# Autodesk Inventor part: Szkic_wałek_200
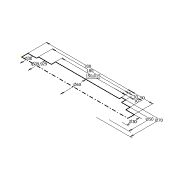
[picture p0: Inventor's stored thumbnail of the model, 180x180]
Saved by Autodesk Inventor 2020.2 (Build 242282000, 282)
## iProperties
Created: 2005-01
Part Number: Szkic_wałek_200
Document SubType Name: Modeling
Designer: F.Stasiak
Manufacturer: Standard
Standards Organization: Custom
Density: 1 g/cm^3
Material: Ogólny
Appearance: Domyślna
Manager: www.cadconsulting.pl
Company: Fabian Stasiak CAD Consulting
Author: F.Stasiak
Subject: Zbiór ćwiczeń. Autodesk Inventor 2020. Kurs podstawowy
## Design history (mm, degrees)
sketch "Szkic1"
  geometry: L1 (0, 0)-(0, 15); L2 (0, 15)-(20, 15); L3 (20, 15)-(20, 19.965); L4 (20, 19.965)-(49.985, 19.965); L5 (49.985, 19.965)-(49.985, 30); L6 (49.985, 30)-(200, 30); L7 (200, 30)-(200, 35); L8 (200, 35)-(210, 35); L9 (210, 35)-(210, 25); L10 (210, 25)-(230, 25); L11 (230, 25)-(230, 15); L12 (230, 15)-(250, 15); L13 (250, 15)-(250, 0); L14 (0, 0)-(250, 0); 1 further point
  constraints: 28 end point, 10 parallel, 2 perpendicular, 1 coincident, 1 collinear, 1 vertical
  dimensions: "d44" = 10 distance between parallel lines of L9 L7; "d45" = 30 distance between parallel lines of L11 L7; "d46" = 50 distance between parallel lines of L13 L7; "d47" = 150 dimension on L5 L7; "d48" = 180 distance between parallel lines of L3 L7; "d49" = 200 distance between parallel lines of L7 L1; "d50" = 30 diameter of L2 L14; "d51" = 40 dimension on L4 L14; "d52" = 60 diameter of L6 L14; "d53" = 30 diameter of L12 L14; "d54" = 50 diameter of L10 L14; "d55" = 70 diameter of L8 L14
node "Korpusy bryłowe"
node "Korpusy powierzchniowe"
